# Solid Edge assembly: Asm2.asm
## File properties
Author: Deepak Maini
Template: Normal.asm
Last saved by: MYPC
Revision: 8
Application: Solid Edge
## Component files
Part1.par
Part2.par
Part3.par
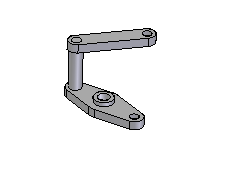
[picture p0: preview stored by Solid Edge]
